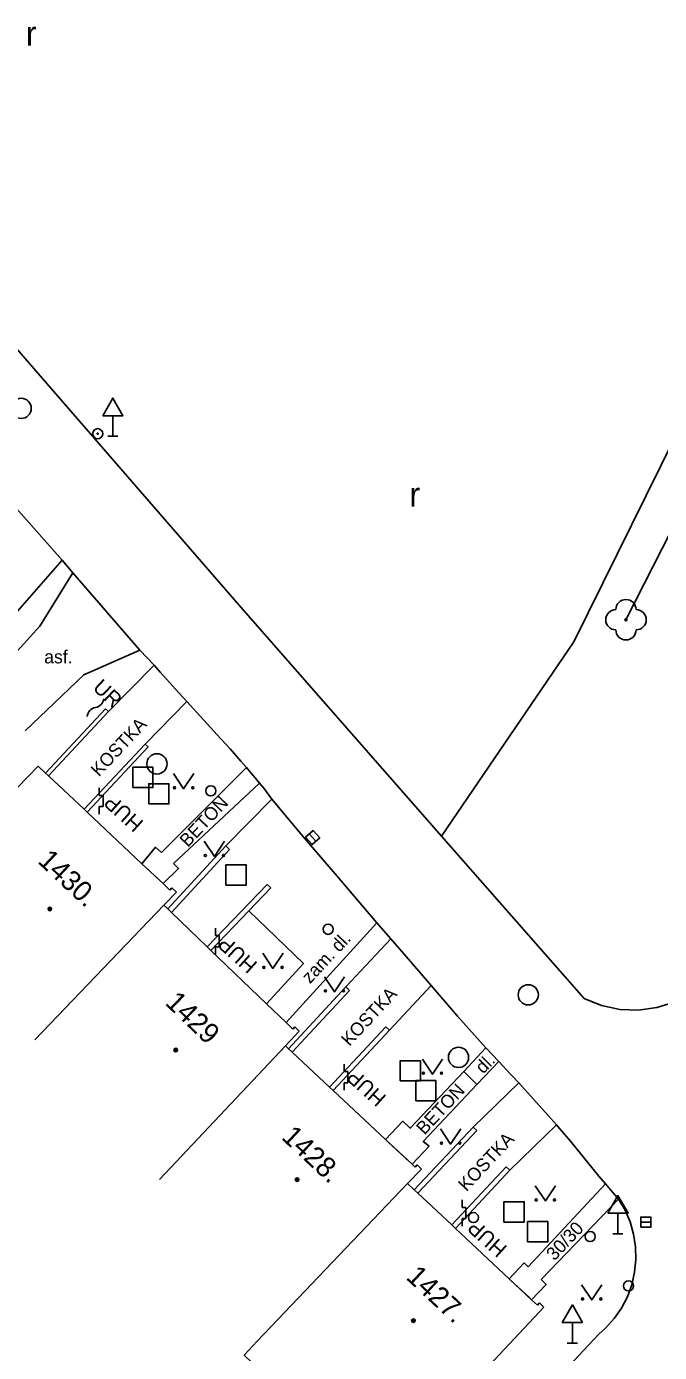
# Model space of a CAD drawing. Extents: x -539244 to -537359, y -1183785 to -1181851.
# Drawn here: x -538237.7 to -538206.4, y -1183727 to -1183661.5 of the extents above; entities that cross this region are included whole.
import ezdxf

# ---------------------------------------------------------------- set-up
doc = ezdxf.new("R2010")
doc.units = 0
for name, color, linetype in [('Vrstva 10', 7, 'Continuous'), ('Vrstva 11', 7, 'Continuous'), ('Vrstva 21', 7, 'Continuous'), ('Vrstva 22', 7, 'Continuous'), ('Vrstva 23', 7, 'Continuous'), ('Vrstva 24', 7, 'Continuous'), ('Vrstva 25', 7, 'Continuous'), ('Vrstva 26', 7, 'Continuous'), ('Vrstva 27', 7, 'Continuous'), ('Vrstva 28', 7, 'Continuous'), ('Vrstva 31', 7, 'Continuous'), ('Vrstva 34', 7, 'Continuous'), ('Vrstva 36', 7, 'Continuous'), ('Vrstva 39', 7, 'Continuous'), ('Vrstva 40', 7, 'Continuous'), ('Vrstva 41', 7, 'Continuous'), ('Vrstva 47', 7, 'Continuous'), ('Vrstva 5', 7, 'Continuous'), ('Vrstva 6', 7, 'Continuous'), ('Vrstva 7', 7, 'Continuous')]:
    doc.layers.add(name, color=color, linetype=linetype)

msp = doc.modelspace()

# ---------------------------------------------------------------- linework, layer by layer
at = {"layer": 'Vrstva 10'}
for p, q in [((-538246.87, -1183667.42), (-538227.24, -1183690.02)), ((-538232.11, -1183692.27), (-538235.42, -1183688.46)), ((-538227.24, -1183690.02), (-538217.2, -1183701.46)), ((-538231.41, -1183693.02), (-538232.11, -1183692.27)), ((-538217.2, -1183701.46), (-538210.15, -1183709.48)), ((-538215.01, -1183711.92), (-538216.42, -1183710.347)), ((-538215.01, -1183711.92), (-538214.38, -1183712.59)), ((-538209.433, -1183726.06), (-538213.525, -1183730.418))]:
    msp.add_line(p, q, dxfattribs=at)
for points in [[(-538235.42, -1183688.46), (-538235.96, -1183687.83), (-538238.34, -1183685.12), (-538241.582, -1183681.465)], [(-538230.186, -1183694.382), (-538230.801, -1183693.704), (-538231.106, -1183693.362), (-538231.41, -1183693.02)], [(-538228.126, -1183696.635), (-538228.949, -1183695.733), (-538229.791, -1183694.813), (-538230.186, -1183694.382)], [(-538225.6, -1183699.63), (-538225.987, -1183699.095), (-538226.2, -1183698.839), (-538226.415, -1183698.579), (-538226.631, -1183698.324), (-538226.85, -1183698.07), (-538227.13, -1183697.75), (-538227.659, -1183697.154), (-538228.126, -1183696.635)], [(-538222.37, -1183703.435), (-538223.68, -1183701.91), (-538223.882, -1183701.673), (-538224.256, -1183701.225), (-538224.58, -1183700.83), (-538225.6, -1183699.63)], [(-538220.4, -1183705.74), (-538221.06, -1183704.96), (-538222.37, -1183703.435)], [(-538216.42, -1183710.347), (-538217.718, -1183708.842), (-538218.741, -1183707.655), (-538219.708, -1183706.53), (-538220.4, -1183705.74)], [(-538210.15, -1183709.48), (-538209.297, -1183709.826), (-538208.397, -1183710.02), (-538207.477, -1183710.055), (-538206.564, -1183709.931), (-538205.81, -1183709.7)], [(-538209.431, -1183718.25), (-538210.825, -1183716.519), (-538211.459, -1183715.793), (-538211.521, -1183715.722), (-538211.937, -1183715.251), (-538212.661, -1183714.443), (-538213.39, -1183713.64), (-538213.48, -1183713.543), (-538213.652, -1183713.366), (-538213.805, -1183713.214), (-538214.38, -1183712.59)], [(-538209.431, -1183718.25), (-538209.102, -1183718.634), (-538208.458, -1183719.384)], [(-538208.458, -1183719.384), (-538208.137, -1183719.928), (-538207.887, -1183720.509), (-538207.712, -1183721.116), (-538207.616, -1183721.74), (-538207.599, -1183722.372), (-538207.662, -1183723.001), (-538207.804, -1183723.616), (-538208.022, -1183724.209), (-538208.314, -1183724.77), (-538208.674, -1183725.289), (-538209.096, -1183725.759), (-538209.433, -1183726.06)]]:
    msp.add_lwpolyline(points, dxfattribs=at)
at = {"layer": 'Vrstva 11'}
for p, q in [((-538235.96, -1183687.83), (-538240.43, -1183692.92)), ((-538233.66, -1183695.3), (-538231.41, -1183693.02)), ((-538231.86, -1183696.91), (-538229.791, -1183694.813)), ((-538231.04, -1183702.26), (-538226.85, -1183698.07)), ((-538230.46, -1183702.81), (-538226.2, -1183698.839)), ((-538225.6, -1183699.63), (-538227.86, -1183701.93)), ((-538224.89, -1183710.67), (-538220.4, -1183705.74)), ((-538219.708, -1183706.53), (-538221.93, -1183708.91)), ((-538217.718, -1183708.842), (-538219.78, -1183711.05)), ((-538215.01, -1183711.92), (-538216.1, -1183713.08)), ((-538214.38, -1183712.59), (-538215.46, -1183713.73)), ((-538216.1, -1183713.08), (-538215.46, -1183713.73)), ((-538215.65, -1183715.83), (-538213.39, -1183713.64)), ((-538213.83, -1183717.96), (-538211.521, -1183715.722)), ((-538217.82, -1183716.77), (-538218.658, -1183717.669)), ((-538212.932, -1183722.725), (-538209.102, -1183718.634)), ((-538212.28, -1183723.36), (-538208.458, -1183719.384))]:
    msp.add_line(p, q, dxfattribs=at)
for points in [[(-538235.42, -1183688.46), (-538237.06, -1183691.08), (-538239.95, -1183694.25)], [(-538237.79, -1183696.25), (-538234.89, -1183693.49), (-538232.11, -1183692.27)], [(-538231.04, -1183702.26), (-538231.34, -1183702.01), (-538232.02, -1183702.82)], [(-538230.46, -1183702.81), (-538230.2, -1183703.05), (-538230.97, -1183703.8)], [(-538225.86, -1183709.74), (-538224.03, -1183707.75), (-538226.73, -1183705.15)], [(-538216.1, -1183713.08), (-538218.75, -1183715.89), (-538219.12, -1183715.54), (-538219.967, -1183716.447)], [(-538215.46, -1183713.73), (-538218.106, -1183716.536), (-538217.82, -1183716.77)], [(-538212.932, -1183722.725), (-538213.12, -1183722.54), (-538213.857, -1183723.327)], [(-538212.28, -1183723.36), (-538212.04, -1183723.6), (-538212.752, -1183724.361)]]:
    msp.add_lwpolyline(points, dxfattribs=at)
at = {"layer": 'Vrstva 21'}
msp.add_line((-538208.09, -1183690.77), (-538194.78, -1183664.52), dxfattribs=at)
at = {"layer": 'Vrstva 22'}
msp.add_circle((-538208.09, -1183690.77), 0.05, dxfattribs=at)
for centre, start, end in [((-538208.59, -1183690.77), 90, 270), ((-538208.09, -1183690.27), 0, 180), ((-538207.59, -1183690.77), 270, 90), ((-538208.09, -1183691.27), 180, 0)]:
    msp.add_arc(centre, 0.5, start, end, dxfattribs=at)
at = {"layer": 'Vrstva 23'}
for p, q in [((-538196.74, -1183663.68), (-538210.67, -1183691.86)), ((-538210.67, -1183691.86), (-538217.2, -1183701.46))]:
    msp.add_line(p, q, dxfattribs=at)
at = {"layer": 'Vrstva 24'}
for p, q in [((-538234.119, -1183699.449), (-538234.12, -1183699.081)), ((-538233.936, -1183699.45), (-538234.119, -1183699.449)), ((-538233.936, -1183700.002), (-538233.936, -1183699.45)), ((-538234.12, -1183700.37), (-538234.119, -1183700.002)), ((-538234.119, -1183700.002), (-538233.936, -1183700.002)), ((-538228.379, -1183706.369), (-538228.38, -1183706.001)), ((-538228.196, -1183706.37), (-538228.379, -1183706.369)), ((-538228.196, -1183706.922), (-538228.196, -1183706.37)), ((-538228.38, -1183707.29), (-538228.379, -1183706.922)), ((-538228.379, -1183706.922), (-538228.196, -1183706.922)), ((-538222.019, -1183713.089), (-538222.02, -1183712.721)), ((-538221.836, -1183713.09), (-538222.019, -1183713.089)), ((-538221.836, -1183713.642), (-538221.836, -1183713.09)), ((-538222.02, -1183714.01), (-538222.019, -1183713.642)), ((-538222.019, -1183713.642), (-538221.836, -1183713.642)), ((-538216.189, -1183719.799), (-538216.19, -1183719.431)), ((-538216.006, -1183719.8), (-538216.189, -1183719.799)), ((-538216.006, -1183720.352), (-538216.006, -1183719.8)), ((-538216.19, -1183720.72), (-538216.189, -1183720.352)), ((-538216.189, -1183720.352), (-538216.006, -1183720.352))]:
    msp.add_line(p, q, dxfattribs=at)
for centre, start, end in [((-538234.397, -1183694.614), 279.87131, 353.61111), ((-538234.225, -1183695.599), 99.87132, 173.61111)]:
    msp.add_arc(centre, 0.5, start, end, dxfattribs=at)
at = {"layer": 'Vrstva 25'}
for radius in [0.25, 0.0303]:
    msp.add_circle((-538234.2, -1183681.58), radius, dxfattribs=at)
at = {"layer": 'Vrstva 26'}
for points in [[(-538232.47, -1183699.06), (-538231.47, -1183699.06), (-538231.47, -1183698.06), (-538232.47, -1183698.06)], [(-538231.68, -1183699.87), (-538230.68, -1183699.87), (-538230.68, -1183698.87), (-538231.68, -1183698.87)], [(-538227.86, -1183703.88), (-538226.86, -1183703.88), (-538226.86, -1183702.88), (-538227.86, -1183702.88)], [(-538219.25, -1183713.55), (-538218.25, -1183713.55), (-538218.25, -1183712.55), (-538219.25, -1183712.55)], [(-538218.48, -1183714.53), (-538217.48, -1183714.53), (-538217.48, -1183713.53), (-538218.48, -1183713.53)], [(-538214.12, -1183720.52), (-538213.12, -1183720.52), (-538213.12, -1183719.52), (-538214.12, -1183719.52)], [(-538212.95, -1183721.5), (-538211.95, -1183721.5), (-538211.95, -1183720.5), (-538212.95, -1183720.5)]]:
    msp.add_lwpolyline(points, close=True, dxfattribs=at)
at = {"layer": 'Vrstva 27'}
for p, q in [((-538223.743, -1183701.34), (-538223.413, -1183701.714)), ((-538207.357, -1183720.527), (-538206.857, -1183720.527))]:
    msp.add_line(p, q, dxfattribs=at)
for points in [[(-538223.931, -1183701.505), (-538223.6, -1183701.88), (-538223.225, -1183701.549), (-538223.556, -1183701.174)], [(-538207.357, -1183720.777), (-538206.857, -1183720.777), (-538206.857, -1183720.277), (-538207.357, -1183720.277)]]:
    msp.add_lwpolyline(points, close=True, dxfattribs=at)
for centre in [(-538237.984, -1183680.33), (-538231.27, -1183697.89), (-538212.919, -1183709.296), (-538216.366, -1183712.385)]:
    msp.add_circle(centre, 0.5, dxfattribs=at)
at = {"layer": 'Vrstva 28'}
for centre in [(-538228.61, -1183699.22), (-538222.81, -1183706.06), (-538209.863, -1183721.234), (-538207.967, -1183723.675)]:
    msp.add_circle(centre, 0.25, dxfattribs=at)
at = {"layer": 'Vrstva 31'}
msp.add_circle((-538215.63, -1183720.3), 0.25, dxfattribs=at)
at = {"layer": 'Vrstva 34'}
for p, q in [((-538233.45, -1183680.692), (-538233.45, -1183681.71)), ((-538233.7, -1183681.71), (-538233.2, -1183681.71)), ((-538208.489, -1183720.082), (-538208.489, -1183721.1)), ((-538208.739, -1183721.1), (-538208.239, -1183721.1)), ((-538210.739, -1183725.477), (-538210.739, -1183726.495)), ((-538210.989, -1183726.495), (-538210.489, -1183726.495))]:
    msp.add_line(p, q, dxfattribs=at)
for points in [[(-538233.95, -1183680.692), (-538232.95, -1183680.692), (-538233.45, -1183679.826)], [(-538208.989, -1183720.082), (-538207.989, -1183720.082), (-538208.489, -1183719.216)], [(-538211.239, -1183725.477), (-538210.239, -1183725.477), (-538210.739, -1183724.611)]]:
    msp.add_lwpolyline(points, close=True, dxfattribs=at)
at = {"layer": 'Vrstva 36'}
for points in [[(-538230.451, -1183698.367), (-538229.951, -1183699.117), (-538229.451, -1183698.367)], [(-538228.929, -1183701.713), (-538228.429, -1183702.463), (-538227.929, -1183701.713)], [(-538226.038, -1183707.24), (-538225.538, -1183707.99), (-538225.038, -1183707.24)], [(-538222.998, -1183708.403), (-538222.498, -1183709.153), (-538221.998, -1183708.403)], [(-538218.153, -1183712.468), (-538217.653, -1183713.218), (-538217.153, -1183712.468)], [(-538217.258, -1183715.919), (-538216.758, -1183716.669), (-538216.258, -1183715.919)], [(-538212.575, -1183718.73), (-538212.075, -1183719.48), (-538211.575, -1183718.73)], [(-538210.283, -1183723.619), (-538209.783, -1183724.369), (-538209.283, -1183723.619)]]:
    msp.add_lwpolyline(points, dxfattribs=at)
for centre in [(-538230.401, -1183699.067), (-538229.502, -1183699.067), (-538228.879, -1183702.413), (-538227.98, -1183702.413), (-538225.988, -1183707.94), (-538225.089, -1183707.94), (-538222.948, -1183709.103), (-538222.049, -1183709.103), (-538218.103, -1183713.168), (-538217.204, -1183713.168), (-538217.208, -1183716.619), (-538216.309, -1183716.619), (-538212.525, -1183719.43), (-538211.626, -1183719.43), (-538210.233, -1183724.319), (-538209.334, -1183724.319)]:
    msp.add_circle(centre, 0.05, dxfattribs=at)
at = {"layer": 'Vrstva 39'}
for centre, radius in [((-538236.565, -1183705.057), 0.09), ((-538236.565, -1183705.057), 0.0398), ((-538230.341, -1183712.027), 0.09), ((-538230.341, -1183712.027), 0.0398), ((-538224.346, -1183718.426), 0.09), ((-538224.346, -1183718.426), 0.0398), ((-538218.593, -1183725.39), 0.09), ((-538218.593, -1183725.39), 0.0398)]:
    msp.add_circle(centre, radius, dxfattribs=at)
at = {"layer": 'Vrstva 5'}
for p, q in [((-538237.14, -1183698), (-538244.23, -1183705.3)), ((-538230.631, -1183704.124), (-538230.528, -1183704.014)), ((-538230.31, -1183704.22), (-538230.528, -1183704.014)), ((-538224.56, -1183710.99), (-538224.456, -1183710.882)), ((-538224.24, -1183711.09), (-538224.456, -1183710.882)), ((-538218.512, -1183717.805), (-538218.409, -1183717.695)), ((-538218.19, -1183717.9), (-538218.409, -1183717.695)), ((-538215.568, -1183728.37), (-538212.15, -1183724.72)), ((-538212.471, -1183724.624), (-538212.368, -1183724.514)), ((-538212.15, -1183724.72), (-538212.368, -1183724.514))]:
    msp.add_line(p, q, dxfattribs=at)
for points in [[(-538230.631, -1183704.124), (-538230.97, -1183703.8), (-538232.02, -1183702.82), (-538234.726, -1183700.271), (-538234.872, -1183700.134), (-538236.63, -1183698.479), (-538236.776, -1183698.342), (-538237.14, -1183698)], [(-538237.31, -1183711.52), (-538230.926, -1183704.875), (-538230.31, -1183704.22)], [(-538224.56, -1183710.99), (-538224.89, -1183710.67), (-538225.86, -1183709.74), (-538228.609, -1183707.1), (-538228.79, -1183706.927), (-538230.556, -1183705.23), (-538230.737, -1183705.057), (-538230.926, -1183704.875)], [(-538231.14, -1183718.42), (-538224.925, -1183711.818), (-538224.24, -1183711.09)], [(-538218.512, -1183717.805), (-538218.658, -1183717.669), (-538219.967, -1183716.447), (-538222.559, -1183714.027), (-538222.741, -1183713.856), (-538224.592, -1183712.128), (-538224.775, -1183711.958), (-538224.925, -1183711.818)], [(-538226.32, -1183726.41), (-538218.881, -1183718.623), (-538218.19, -1183717.9)], [(-538212.471, -1183724.624), (-538212.752, -1183724.361), (-538213.857, -1183723.327), (-538216.52, -1183720.833), (-538216.702, -1183720.662), (-538218.37, -1183719.101), (-538218.552, -1183718.93), (-538218.881, -1183718.623)], [(-538226.32, -1183726.41), (-538226.96, -1183727.09), (-538220.4, -1183733.36)]]:
    msp.add_lwpolyline(points, dxfattribs=at)
at = {"layer": 'Vrstva 6'}
for p, q in [((-538234.872, -1183700.134), (-538236.63, -1183698.479)), ((-538231.11, -1183703.67), (-538231.87, -1183702.96)), ((-538228.79, -1183706.927), (-538230.556, -1183705.23)), ((-538224.89, -1183710.67), (-538225.86, -1183709.74)), ((-538222.741, -1183713.856), (-538224.592, -1183712.128)), ((-538218.79, -1183717.54), (-538219.84, -1183716.57)), ((-538216.702, -1183720.662), (-538218.37, -1183719.101)), ((-538212.85, -1183724.27), (-538213.79, -1183723.39))]:
    msp.add_line(p, q, dxfattribs=at)
at = {"layer": 'Vrstva 7'}
for p, q in [((-538233.806, -1183695.163), (-538236.776, -1183698.342)), ((-538233.66, -1183695.3), (-538236.63, -1183698.479)), ((-538233.66, -1183695.3), (-538233.806, -1183695.163)), ((-538231.86, -1183696.91), (-538234.872, -1183700.134)), ((-538231.713, -1183697.046), (-538231.86, -1183696.91)), ((-538231.713, -1183697.046), (-538234.726, -1183700.271)), ((-538230.737, -1183705.057), (-538227.86, -1183701.93)), ((-538230.556, -1183705.23), (-538227.68, -1183702.12)), ((-538227.86, -1183701.93), (-538227.68, -1183702.12)), ((-538228.79, -1183706.927), (-538225.831, -1183703.846)), ((-538226.73, -1183705.15), (-538225.65, -1183704.02)), ((-538225.831, -1183703.846), (-538225.65, -1183704.02)), ((-538228.609, -1183707.1), (-538226.73, -1183705.15)), ((-538224.775, -1183711.958), (-538221.93, -1183708.91)), ((-538224.592, -1183712.128), (-538221.747, -1183709.08)), ((-538221.747, -1183709.08), (-538221.93, -1183708.91)), ((-538222.741, -1183713.856), (-538219.962, -1183710.879)), ((-538222.559, -1183714.027), (-538219.78, -1183711.05)), ((-538219.78, -1183711.05), (-538219.962, -1183710.879)), ((-538218.552, -1183718.93), (-538215.65, -1183715.83)), ((-538215.467, -1183716), (-538215.65, -1183715.83)), ((-538218.37, -1183719.101), (-538215.467, -1183716)), ((-538216.702, -1183720.662), (-538214.012, -1183717.789)), ((-538213.83, -1183717.96), (-538214.012, -1183717.789)), ((-538216.52, -1183720.833), (-538213.83, -1183717.96))]:
    msp.add_line(p, q, dxfattribs=at)

# ---------------------------------------------------------------- texts
at = {"layer": 'Vrstva 36'}
for p in [(-538237.752, -1183662.408), (-538218.796, -1183685.18)]:
    msp.add_text('r', height=1.2, dxfattribs=at).set_placement(p)
at = {"layer": 'Vrstva 40'}
msp.add_text('asf.', height=0.65, dxfattribs=at).set_placement((-538236.842, -1183692.927))
for s, rotation, p in [('KOSTKA', 46.94709, (-538234.134, -1183698.558)), ('BETON', 46.74248, (-538229.743, -1183702.041)), ('zam. dl.', 46.87689, (-538223.712, -1183708.782)), ('KOSTKA', 46.97013, (-538221.759, -1183711.874)), ('dl.', 45.03359, (-538215.15, -1183713.235)), ('BETON', 46.97154, (-538218.048, -1183716.252)), ('KOSTKA', 46.88412, (-538215.974, -1183719.044)), ('30/30', 46.89171, (-538211.622, -1183722.466))]:
    msp.add_text(s, height=0.65, rotation=rotation, dxfattribs=at).set_placement(p)
at = {"layer": 'Vrstva 41'}
for s, rotation, p in [('UR', 316.78484, (-538234.489, -1183694.183)), ('HUP', 137.95777, (-538231.883, -1183700.762)), ('HUP', 137.95777, (-538226.255, -1183707.747)), ('HUP', 137.95777, (-538219.886, -1183714.324)), ('HUP', 137.95777, (-538213.914, -1183721.765))]:
    msp.add_text(s, height=0.75, rotation=rotation, dxfattribs=at).set_placement(p)
at = {"layer": 'Vrstva 47'}
for s, rotation, p in [('1430.', 316.74559, (-538237.207, -1183702.743)), ('1429', 316.15209, (-538230.911, -1183709.743)), ('1428.', 316.96984, (-538225.164, -1183716.384)), ('1427.', 316.88545, (-538219.012, -1183723.294))]:
    msp.add_text(s, height=1, rotation=rotation, dxfattribs=at).set_placement(p)

doc.saveas('drawing.dxf')
